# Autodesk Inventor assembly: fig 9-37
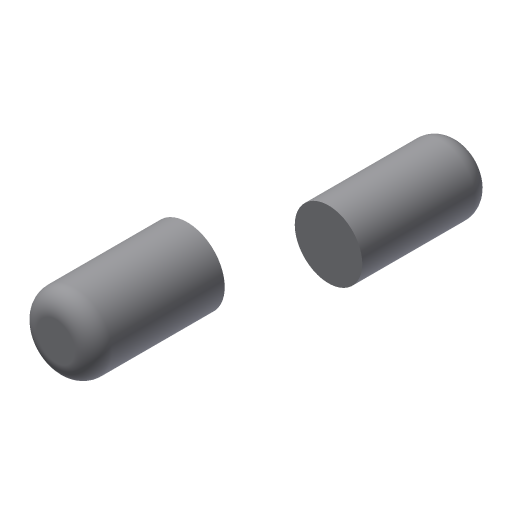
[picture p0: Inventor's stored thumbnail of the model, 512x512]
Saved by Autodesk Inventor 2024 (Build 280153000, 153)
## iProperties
Created: 2013-07
Part Number: fig 9-37
Document SubType Name: Assembly
Designer: CADCIM
Author: CADCIM
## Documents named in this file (3)
- D:\PROJECTS\Project 2023\RESOURCES INVENTOR 2024\RESOURCES INVENTOR 2024\Inventor_2023_Part\Inventor_2024_Part\c09_Inv_2024_prt\fig 9-38.iam
- D:\PROJECTS\Project 2023\RESOURCES INVENTOR 2024\RESOURCES INVENTOR 2024\Inventor_2023_Part\Inventor_2024_Part\c09_Inv_2024_prt\10.ipt
- D:\PROJECTS\Project 2023\RESOURCES INVENTOR 2024\RESOURCES INVENTOR 2024\Inventor_2023_Part\Inventor_2024_Part\c09_Inv_2024_prt\11.ipt
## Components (2 placed, 2 different names)
1. 10:1
2. 11:1
